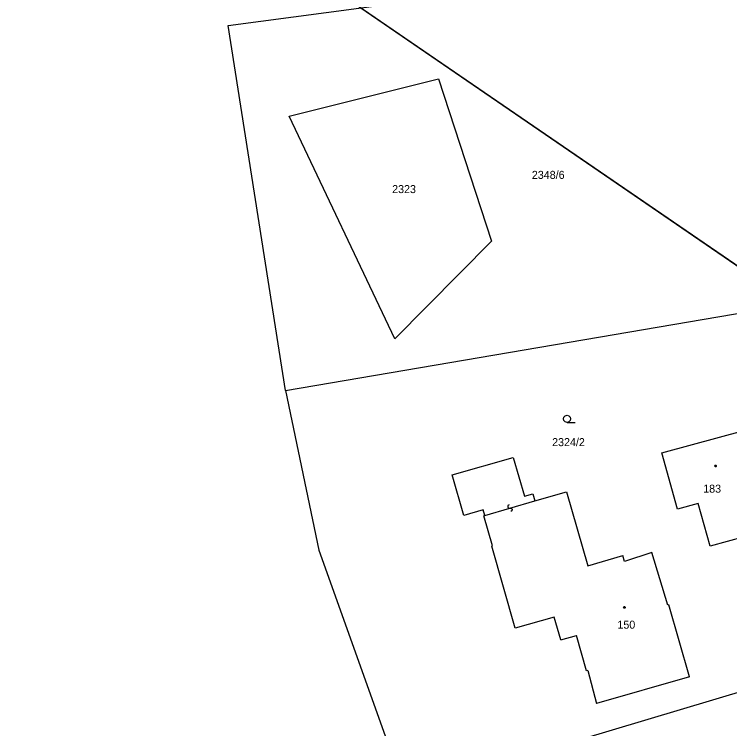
# Model space of a CAD drawing. Extents: x -747792 to -745414, y -1093712 to -1091463.
# Drawn here: x -746720.5 to -746644.6, y -1092850.4 to -1092774.6 of the extents above; entities that cross this region are included whole.
import ezdxf

# ---------------------------------------------------------------- set-up
doc = ezdxf.new("R2010")
doc.units = 0
for name, color, linetype in [('Budovy', 7, 'Continuous'), ('Koleje_dopravní prvky', 7, 'Continuous'), ('Kultury', 7, 'Continuous'), ('Ploty_opěrné zdi', 7, 'Continuous'), ('Stromy_porost', 7, 'Continuous'), ('Značky IS', 7, 'Continuous')]:
    doc.layers.add(name, color=color, linetype=linetype)

msp = doc.modelspace()

# ---------------------------------------------------------------- linework, layer by layer
at = {"layer": 'Budovy'}
msp.add_lwpolyline([(-746661.84, -1092817.91), (-746662.03, -1092817.86), (-746662.165, -1092817.72), (-746662.215, -1092817.535), (-746662.165, -1092817.35), (-746662.03, -1092817.21), (-746661.84, -1092817.16), (-746661.65, -1092817.21), (-746661.515, -1092817.35), (-746661.465, -1092817.535), (-746661.515, -1092817.72), (-746661.65, -1092817.86), (-746661.84, -1092817.91), (-746660.965, -1092817.91)], dxfattribs=at)
at = {"layer": 'Kultury'}
for points in [[(-746670.56, -1092827.78), (-746665.25, -1092826.25)], [(-746667.985, -1092826.648), (-746668.115, -1092826.737), (-746668.13, -1092826.903), (-746668.025, -1092827.013), (-746667.771, -1092827.028), (-746667.675, -1092827.146), (-746667.702, -1092827.305), (-746667.825, -1092827.382)]]:
    msp.add_lwpolyline(points, dxfattribs=at)
at = {"layer": 'Ploty_opěrné zdi'}
for points in [[(-746646.08, -1092822.445), (-746646.03, -1092822.455), (-746646.005, -1092822.5), (-746645.995, -1092822.53), (-746646.005, -1092822.575), (-746646.045, -1092822.61), (-746646.08, -1092822.615), (-746646.125, -1092822.6), (-746646.155, -1092822.57), (-746646.165, -1092822.53), (-746646.155, -1092822.485), (-746646.115, -1092822.45)], [(-746655.75, -1092837.455), (-746655.7, -1092837.465), (-746655.675, -1092837.51), (-746655.665, -1092837.54), (-746655.675, -1092837.585), (-746655.715, -1092837.62), (-746655.75, -1092837.625), (-746655.795, -1092837.61), (-746655.825, -1092837.58), (-746655.835, -1092837.54), (-746655.825, -1092837.495), (-746655.785, -1092837.46)]]:
    msp.add_lwpolyline(points, close=True, dxfattribs=at)
at = {"layer": 'Stromy_porost'}
for points in [[(-746697.83, -1092775.8), (-746680.49, -1092773.48)], [(-746691.72, -1092814.54), (-746697.83, -1092775.8)], [(-746691.34, -1092785.42), (-746675.48, -1092781.44)], [(-746675.48, -1092781.44), (-746669.85, -1092798.67)], [(-746680.12, -1092809.03), (-746691.34, -1092785.42)], [(-746669.85, -1092798.67), (-746680.12, -1092809.03)], [(-746691.72, -1092814.54), (-746636.26, -1092805.07)], [(-746691.72, -1092814.54), (-746688.21, -1092831.48)], [(-746670.56, -1092827.78), (-746670.73, -1092827.19), (-746672.81, -1092827.78), (-746674.03, -1092823.46), (-746667.55, -1092821.62), (-746666.37, -1092825.75), (-746665.46, -1092825.49), (-746665.25, -1092826.25)], [(-746665.25, -1092826.25), (-746661.89, -1092825.29)], [(-746661.89, -1092825.29), (-746659.62, -1092833.14)], [(-746670.67, -1092827.81), (-746670.56, -1092827.78)], [(-746669.74, -1092831.02), (-746670.67, -1092827.81)], [(-746669.84, -1092831.06), (-746669.74, -1092831.02)], [(-746667.34, -1092839.76), (-746669.84, -1092831.06)], [(-746688.21, -1092831.48), (-746679.02, -1092857.11)], [(-746652.84, -1092831.7), (-746655.73, -1092832.66)], [(-746651.14, -1092837.3), (-746652.84, -1092831.7)], [(-746659.62, -1092833.14), (-746655.91, -1092832.05)], [(-746655.73, -1092832.66), (-746655.91, -1092832.05)], [(-746651.02, -1092837.27), (-746651.14, -1092837.3)], [(-746648.83, -1092844.92), (-746651.02, -1092837.27)], [(-746663.19, -1092838.58), (-746667.34, -1092839.76)], [(-746662.51, -1092840.99), (-746663.19, -1092838.58)], [(-746662.51, -1092840.99), (-746660.83, -1092840.52)], [(-746659.76, -1092844.28), (-746660.83, -1092840.52)], [(-746679.02, -1092857.11), (-746627.76, -1092841.79)], [(-746659.64, -1092844.25), (-746659.76, -1092844.28)], [(-746659.64, -1092844.25), (-746658.71, -1092847.75)], [(-746648.83, -1092844.92), (-746658.71, -1092847.75)]]:
    msp.add_lwpolyline(points, dxfattribs=at)
msp.add_lwpolyline([(-746651.78, -1092821.13), (-746642.78, -1092818.69), (-746640.51, -1092826.83), (-746638.31, -1092826.2), (-746637.63, -1092828.58), (-746646.65, -1092831.03), (-746647.9, -1092826.52), (-746650.12, -1092827.13)], close=True, dxfattribs=at)
at = {"layer": 'Značky IS'}
msp.add_lwpolyline([(-746735.166, -1092738.694), (-746640.77, -1092803.34), (-746689.412, -1092770.028)], dxfattribs=at)

# ---------------------------------------------------------------- texts
at = {"layer": 'Koleje_dopravní prvky'}
for s, p in [('2348/6', (-746665.575, -1092792.07)), ('2323', (-746680.412, -1092793.58)), ('2324/2', (-746663.425, -1092820.43)), ('183', (-746647.38, -1092825.37)), ('150', (-746656.49, -1092839.8))]:
    msp.add_text(s, height=0.85, dxfattribs=at).set_placement(p)

doc.saveas('drawing.dxf')
